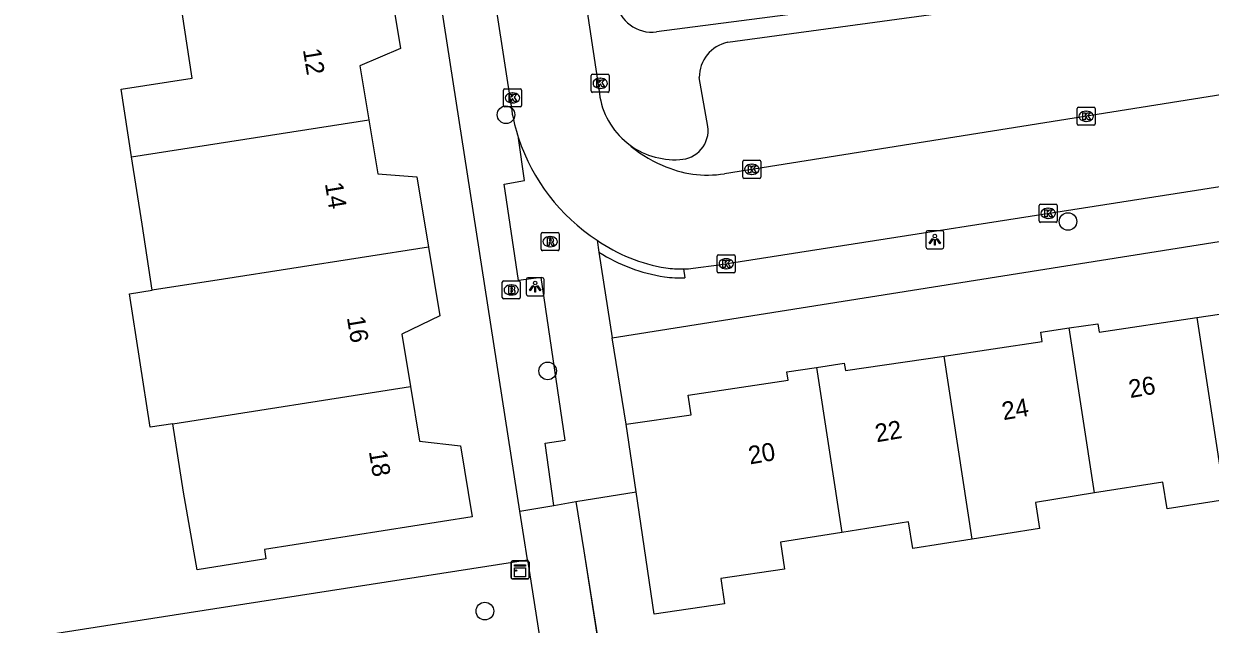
# Model space of a CAD drawing. Extents: x 160077 to 160945, y 386481 to 387498.
# Drawn here: x 160424.3 to 160490.2, y 387113 to 387146.3 of the extents above; entities that cross this region are included whole.
import ezdxf

# ---------------------------------------------------------------- set-up
doc = ezdxf.new("R2010")
doc.units = 0
for name, color, linetype in [('IMGEO_Boom', 7, 'Continuous'), ('IMGEO_Brandkraan', 7, 'Continuous'), ('IMGEO_Groenvoorziening', 7, 'Continuous'), ('IMGEO_Kast', 7, 'Continuous'), ('IMGEO_Kolk', 7, 'Continuous'), ('IMGEO_Lichtpunt', 7, 'Continuous'), ('IMGEO_Muur', 7, 'Continuous'), ('IMGEO_Pand', 7, 'Continuous'), ('IMGEO_Pand_nummerreeks', 7, 'Continuous'), ('IMGEO_Rijbaan_lokaal_open', 7, 'Continuous'), ('IMGEO_Rioolput', 7, 'Continuous'), ('IMGEO_Voetpad_open', 7, 'Continuous')]:
    doc.layers.add(name, color=color, linetype=linetype)

msp = doc.modelspace()

# ---------------------------------------------------------------- linework, layer by layer
at = {"layer": 'IMGEO_Boom'}
for centre in [(160451.086, 387141.291), (160482.283, 387135.372), (160453.398, 387127.085), (160449.914, 387113.767)]:
    msp.add_circle(centre, 0.489, dxfattribs=at)
at = {"layer": 'IMGEO_Brandkraan'}
for p, q in [((160450.879, 387131.15), (160450.879, 387132.002)), ((160450.954, 387132.076), (160451.806, 387132.076)), ((160451.88, 387132.002), (160451.88, 387131.15)), ((160451.39, 387131.296), (160451.365, 387131.296)), ((160451.367, 387131.856), (160451.392, 387131.856)), ((160451.806, 387131.076), (160450.954, 387131.076))]:
    msp.add_line(p, q, dxfattribs=at)
for points in [[(160450.879, 387131.15), (160450.879, 387132.002)], [(160450.954, 387132.076), (160451.806, 387132.076)], [(160451.88, 387132.002), (160451.88, 387131.15)], [(160451.227, 387131.776), (160451.227, 387131.376), (160451.44, 387131.376)], [(160451.458, 387131.776), (160451.227, 387131.776)], [(160451.406, 387131.695), (160451.352, 387131.695), (160451.352, 387131.619)], [(160451.352, 387131.619), (160451.405, 387131.619)], [(160451.414, 387131.543), (160451.352, 387131.543), (160451.352, 387131.462)], [(160451.352, 387131.462), (160451.414, 387131.462)], [(160451.806, 387131.076), (160450.954, 387131.076)]]:
    msp.add_lwpolyline(points, dxfattribs=at)
for centre, radius, start, end in [((160450.956, 387132), 0.0765, 91.55205, 178.44795), ((160450.956, 387132), 0.0765, 91.55205, 178.44795), ((160451.804, 387132), 0.0765, 1.55205, 88.44795), ((160451.804, 387132), 0.0765, 1.55205, 88.44795), ((160451.407, 387131.657), 0.0379, 267.82845, 90.93552), ((160451.415, 387131.502), 0.0404, 269.87594, 90.50774), ((160451.446, 387131.627), 0.251, 268.66757, 293.53466), ((160451.462, 387131.631), 0.145, 59.4692, 91.53667), ((160451.487, 387131.678), 0.0922, 285.51372, 58.15012), ((160451.492, 387131.486), 0.105, 301.31148, 78.98903), ((160450.956, 387131.152), 0.0765, 181.55205, 268.44795), ((160450.956, 387131.152), 0.0765, 181.55205, 268.44795), ((160451.804, 387131.152), 0.0765, 271.55205, 358.44795), ((160451.804, 387131.152), 0.0765, 271.55205, 358.44795)]:
    msp.add_arc(centre, radius, start, end, dxfattribs=at)
for centre, major_axis, ratio, start_param, end_param in [((160451.366, 387131.576), (-0.387, 0.002), 0.722429, 4.712389, 7.853982), ((160451.391, 387131.576), (-0.39, 0.002), 0.717154, 1.570796, 4.712389)]:
    msp.add_ellipse(centre, major_axis=major_axis, ratio=ratio, start_param=start_param, end_param=end_param, dxfattribs=at)
at = {"layer": 'IMGEO_Groenvoorziening'}
msp.add_lwpolyline([(160412.74, 387110.46), (160432.671, 387113.564), (160452.281, 387116.619)], dxfattribs=at)
at = {"layer": 'IMGEO_Kast'}
for p, q in [((160451.367, 387115.623), (160451.367, 387116.464)), ((160451.367, 387116.464), (160451.367, 387115.623)), ((160451.442, 387116.548), (160452.283, 387116.548)), ((160452.283, 387116.548), (160451.442, 387116.548)), ((160452.367, 387116.473), (160452.367, 387115.632)), ((160452.367, 387115.632), (160452.367, 387116.473)), ((160452.292, 387115.548), (160451.451, 387115.548)), ((160451.451, 387115.548), (160452.292, 387115.548))]:
    msp.add_line(p, q, dxfattribs=at)
for points in [[(160451.562, 387116.338), (160452.162, 387116.338), (160452.162, 387116.253), (160451.562, 387116.253), (160451.562, 387116.338)], [(160451.562, 387116.163), (160452.162, 387116.163), (160452.162, 387115.674), (160451.562, 387115.674), (160451.562, 387116.163)]]:
    msp.add_lwpolyline(points, dxfattribs=at)
msp.add_circle((160451.646, 387116.012), 0.0377, dxfattribs=at)
for centre, start, end in [((160451.445, 387116.47), 92.4484, 184.28452), ((160451.445, 387116.47), 92.4484, 184.28452), ((160452.289, 387116.47), 2.4484, 94.28452), ((160452.289, 387116.47), 2.4484, 94.28452), ((160451.445, 387115.626), 182.4484, 274.28452), ((160451.445, 387115.626), 182.4484, 274.28452), ((160452.289, 387115.626), 272.4484, 4.28452), ((160452.289, 387115.626), 272.4484, 4.28452)]:
    msp.add_arc(centre, 0.0779, start, end, dxfattribs=at)
at = {"layer": 'IMGEO_Kolk'}
for p, q in [((160455.816, 387142.609), (160455.816, 387143.461)), ((160455.891, 387143.535), (160456.743, 387143.535)), ((160456.304, 387143.315), (160456.329, 387143.315)), ((160456.817, 387143.461), (160456.817, 387142.609)), ((160450.946, 387141.799), (160450.946, 387142.651)), ((160451.021, 387142.725), (160451.873, 387142.725)), ((160451.434, 387142.505), (160451.459, 387142.505)), ((160451.947, 387142.651), (160451.947, 387141.799)), ((160456.743, 387142.535), (160455.891, 387142.535)), ((160456.327, 387142.755), (160456.302, 387142.755)), ((160451.457, 387141.945), (160451.432, 387141.945)), ((160451.873, 387141.725), (160451.021, 387141.725)), ((160482.789, 387140.78), (160482.789, 387141.632)), ((160482.864, 387141.706), (160483.716, 387141.706)), ((160483.277, 387141.486), (160483.302, 387141.486)), ((160483.79, 387141.632), (160483.79, 387140.78)), ((160483.716, 387140.706), (160482.864, 387140.706)), ((160483.3, 387140.926), (160483.275, 387140.926)), ((160464.231, 387137.838), (160464.231, 387138.69)), ((160464.306, 387138.764), (160465.158, 387138.764)), ((160464.719, 387138.544), (160464.744, 387138.544)), ((160465.232, 387138.69), (160465.232, 387137.838)), ((160464.742, 387137.984), (160464.717, 387137.984)), ((160465.158, 387137.764), (160464.306, 387137.764)), ((160480.685, 387135.4), (160480.685, 387136.252)), ((160480.76, 387136.326), (160481.612, 387136.326)), ((160481.173, 387136.106), (160481.198, 387136.106)), ((160481.686, 387136.252), (160481.686, 387135.4)), ((160481.612, 387135.326), (160480.76, 387135.326)), ((160481.196, 387135.546), (160481.171, 387135.546)), ((160462.811, 387132.602), (160462.811, 387133.454)), ((160462.886, 387133.528), (160463.738, 387133.528)), ((160463.299, 387133.308), (160463.324, 387133.308)), ((160463.812, 387133.454), (160463.812, 387132.602)), ((160463.322, 387132.748), (160463.297, 387132.748)), ((160463.738, 387132.528), (160462.886, 387132.528))]:
    msp.add_line(p, q, dxfattribs=at)
for points in [[(160455.816, 387142.609), (160455.816, 387143.461)], [(160455.891, 387143.535), (160456.743, 387143.535)], [(160456.137, 387143.235), (160456.26, 387143.235), (160456.26, 387143.084), (160456.39, 387143.235), (160456.554, 387143.235), (160456.408, 387143.084), (160456.561, 387142.835), (160456.409, 387142.835), (160456.324, 387142.999), (160456.26, 387142.932), (160456.26, 387142.835), (160456.137, 387142.835), (160456.137, 387143.235)], [(160456.817, 387143.461), (160456.817, 387142.609)], [(160450.946, 387141.799), (160450.946, 387142.651)], [(160451.021, 387142.725), (160451.873, 387142.725)], [(160451.947, 387142.651), (160451.947, 387141.799)], [(160456.743, 387142.535), (160455.891, 387142.535)], [(160451.267, 387142.425), (160451.39, 387142.425), (160451.39, 387142.274), (160451.52, 387142.425), (160451.684, 387142.425), (160451.538, 387142.274), (160451.691, 387142.025), (160451.539, 387142.025), (160451.454, 387142.189), (160451.39, 387142.122), (160451.39, 387142.025), (160451.267, 387142.025), (160451.267, 387142.425)], [(160451.873, 387141.725), (160451.021, 387141.725)], [(160482.789, 387140.78), (160482.789, 387141.632)], [(160482.864, 387141.706), (160483.716, 387141.706)], [(160483.11, 387141.406), (160483.233, 387141.406), (160483.233, 387141.255), (160483.363, 387141.406), (160483.527, 387141.406), (160483.381, 387141.255), (160483.534, 387141.006), (160483.382, 387141.006), (160483.297, 387141.17), (160483.233, 387141.103), (160483.233, 387141.006), (160483.11, 387141.006), (160483.11, 387141.406)], [(160483.79, 387141.632), (160483.79, 387140.78)], [(160483.716, 387140.706), (160482.864, 387140.706)], [(160464.231, 387137.838), (160464.231, 387138.69)], [(160464.306, 387138.764), (160465.158, 387138.764)], [(160465.232, 387138.69), (160465.232, 387137.838)], [(160464.552, 387138.464), (160464.675, 387138.464), (160464.675, 387138.313), (160464.805, 387138.464), (160464.969, 387138.464), (160464.823, 387138.313), (160464.976, 387138.064), (160464.824, 387138.064), (160464.739, 387138.228), (160464.675, 387138.161), (160464.675, 387138.064), (160464.552, 387138.064), (160464.552, 387138.464)], [(160465.158, 387137.764), (160464.306, 387137.764)], [(160480.685, 387135.4), (160480.685, 387136.252)], [(160480.76, 387136.326), (160481.612, 387136.326)], [(160481.006, 387136.026), (160481.129, 387136.026), (160481.129, 387135.875), (160481.259, 387136.026), (160481.423, 387136.026), (160481.277, 387135.875), (160481.43, 387135.626), (160481.278, 387135.626), (160481.193, 387135.79), (160481.129, 387135.723), (160481.129, 387135.626), (160481.006, 387135.626), (160481.006, 387136.026)], [(160481.686, 387136.252), (160481.686, 387135.4)], [(160481.612, 387135.326), (160480.76, 387135.326)], [(160462.811, 387132.602), (160462.811, 387133.454)], [(160462.886, 387133.528), (160463.738, 387133.528)], [(160463.812, 387133.454), (160463.812, 387132.602)], [(160463.132, 387133.228), (160463.255, 387133.228), (160463.255, 387133.077), (160463.385, 387133.228), (160463.549, 387133.228), (160463.403, 387133.077), (160463.556, 387132.828), (160463.404, 387132.828), (160463.319, 387132.992), (160463.255, 387132.925), (160463.255, 387132.828), (160463.132, 387132.828), (160463.132, 387133.228)], [(160463.738, 387132.528), (160462.886, 387132.528)]]:
    msp.add_lwpolyline(points, dxfattribs=at)
for centre, start, end in [((160455.893, 387143.459), 91.55205, 178.44795), ((160455.893, 387143.459), 91.55205, 178.44795), ((160456.741, 387143.459), 1.55205, 88.44795), ((160456.741, 387143.459), 1.55205, 88.44795), ((160451.023, 387142.649), 91.55205, 178.44795), ((160451.023, 387142.649), 91.55205, 178.44795), ((160451.871, 387142.649), 1.55205, 88.44795), ((160451.871, 387142.649), 1.55205, 88.44795), ((160455.893, 387142.611), 181.55205, 268.44795), ((160455.893, 387142.611), 181.55205, 268.44795), ((160456.741, 387142.611), 271.55205, 358.44795), ((160456.741, 387142.611), 271.55205, 358.44795), ((160451.023, 387141.801), 181.55205, 268.44795), ((160451.023, 387141.801), 181.55205, 268.44795), ((160451.871, 387141.801), 271.55205, 358.44795), ((160451.871, 387141.801), 271.55205, 358.44795), ((160482.866, 387141.63), 91.55205, 178.44795), ((160482.866, 387141.63), 91.55205, 178.44795), ((160483.714, 387141.63), 1.55205, 88.44795), ((160483.714, 387141.63), 1.55205, 88.44795), ((160482.866, 387140.782), 181.55205, 268.44795), ((160482.866, 387140.782), 181.55205, 268.44795), ((160483.714, 387140.782), 271.55205, 358.44795), ((160483.714, 387140.782), 271.55205, 358.44795), ((160464.308, 387138.688), 91.55205, 178.44795), ((160464.308, 387138.688), 91.55205, 178.44795), ((160465.156, 387138.688), 1.55205, 88.44795), ((160465.156, 387138.688), 1.55205, 88.44795), ((160464.308, 387137.84), 181.55205, 268.44795), ((160464.308, 387137.84), 181.55205, 268.44795), ((160465.156, 387137.84), 271.55205, 358.44795), ((160465.156, 387137.84), 271.55205, 358.44795), ((160480.762, 387136.25), 91.55205, 178.44795), ((160480.762, 387136.25), 91.55205, 178.44795), ((160481.61, 387136.25), 1.55205, 88.44795), ((160481.61, 387136.25), 1.55205, 88.44795), ((160480.762, 387135.402), 181.55205, 268.44795), ((160480.762, 387135.402), 181.55205, 268.44795), ((160481.61, 387135.402), 271.55205, 358.44795), ((160481.61, 387135.402), 271.55205, 358.44795), ((160462.888, 387133.452), 91.55205, 178.44795), ((160462.888, 387133.452), 91.55205, 178.44795), ((160463.736, 387133.452), 1.55205, 88.44795), ((160463.736, 387133.452), 1.55205, 88.44795), ((160462.888, 387132.604), 181.55205, 268.44795), ((160462.888, 387132.604), 181.55205, 268.44795), ((160463.736, 387132.604), 271.55205, 358.44795), ((160463.736, 387132.604), 271.55205, 358.44795)]:
    msp.add_arc(centre, 0.0765, start, end, dxfattribs=at)
for centre, major_axis, ratio, start_param, end_param in [((160456.303, 387143.035), (-0.387, 0.002), 0.722429, 4.712389, 7.853982), ((160456.328, 387143.035), (-0.39, 0.002), 0.717154, 1.570796, 4.712389), ((160451.433, 387142.225), (-0.387, 0.002), 0.722429, 4.712389, 7.853982), ((160451.458, 387142.225), (-0.39, 0.002), 0.717154, 1.570796, 4.712389), ((160483.276, 387141.206), (-0.387, 0.002), 0.722429, 4.712389, 7.853982), ((160483.301, 387141.206), (-0.39, 0.002), 0.717154, 1.570796, 4.712389), ((160464.718, 387138.264), (-0.387, 0.002), 0.722429, 4.712389, 7.853982), ((160464.743, 387138.264), (-0.39, 0.002), 0.717154, 1.570796, 4.712389), ((160481.172, 387135.826), (-0.387, 0.002), 0.722429, 4.712389, 7.853982), ((160481.197, 387135.826), (-0.39, 0.002), 0.717154, 1.570796, 4.712389), ((160463.298, 387133.028), (-0.387, 0.002), 0.722429, 4.712389, 7.853982), ((160463.323, 387133.028), (-0.39, 0.002), 0.717154, 1.570796, 4.712389)]:
    msp.add_ellipse(centre, major_axis=major_axis, ratio=ratio, start_param=start_param, end_param=end_param, dxfattribs=at)
at = {"layer": 'IMGEO_Lichtpunt'}
for p, q in [((160474.395, 387134.766), (160474.395, 387133.959)), ((160474.395, 387134.766), (160474.395, 387133.959)), ((160475.297, 387134.861), (160474.489, 387134.861)), ((160475.297, 387134.861), (160474.489, 387134.861)), ((160475.391, 387133.959), (160475.391, 387134.766)), ((160475.391, 387133.959), (160475.391, 387134.766)), ((160474.489, 387133.865), (160475.297, 387133.865)), ((160474.489, 387133.865), (160475.297, 387133.865)), ((160452.207, 387132.16), (160452.207, 387131.353)), ((160452.207, 387132.16), (160452.207, 387131.353)), ((160453.109, 387132.255), (160452.301, 387132.255)), ((160453.109, 387132.255), (160452.301, 387132.255)), ((160453.203, 387131.353), (160453.203, 387132.16)), ((160453.203, 387131.353), (160453.203, 387132.16)), ((160452.301, 387131.259), (160453.109, 387131.259)), ((160452.301, 387131.259), (160453.109, 387131.259))]:
    msp.add_line(p, q, dxfattribs=at)
for points in [[(160474.769, 387134.43), (160474.808, 387134.402), (160474.62, 387134.14), (160474.582, 387134.167), (160474.769, 387134.43)], [(160474.871, 387134.382), (160474.918, 387134.382), (160474.918, 387134.06), (160474.871, 387134.06), (160474.871, 387134.382)], [(160474.981, 387134.402), (160475.019, 387134.429), (160475.206, 387134.167), (160475.167, 387134.139), (160474.981, 387134.402)], [(160452.581, 387131.824), (160452.62, 387131.796), (160452.432, 387131.534), (160452.394, 387131.561), (160452.581, 387131.824)], [(160452.683, 387131.776), (160452.73, 387131.776), (160452.73, 387131.454), (160452.683, 387131.454), (160452.683, 387131.776)], [(160452.793, 387131.796), (160452.831, 387131.823), (160453.018, 387131.561), (160452.979, 387131.533), (160452.793, 387131.796)]]:
    msp.add_lwpolyline(points, dxfattribs=at)
for centre in [(160474.894, 387134.564), (160452.706, 387131.958)]:
    msp.add_circle(centre, 0.0994, dxfattribs=at)
for centre, start, end in [((160474.489, 387134.766), 90, 180), ((160474.489, 387134.766), 90, 180), ((160475.297, 387134.766), 0, 90), ((160475.297, 387134.766), 0, 90), ((160474.489, 387133.959), 180, 270), ((160474.489, 387133.959), 180, 270), ((160475.297, 387133.959), 270, 0), ((160475.297, 387133.959), 270, 360), ((160452.301, 387132.16), 90, 180), ((160452.301, 387132.16), 90, 180), ((160453.109, 387132.16), 0, 90), ((160453.109, 387132.16), 0, 90), ((160452.301, 387131.353), 180, 270), ((160452.301, 387131.353), 180, 270), ((160453.109, 387131.353), 270, 0), ((160453.109, 387131.353), 270, 360)]:
    msp.add_arc(centre, 0.0946, start, end, dxfattribs=at)
at = {"layer": 'IMGEO_Muur'}
for points in [[(160454.971, 387119.846), (160455.401, 387117.108)], [(160455.401, 387117.108), (160457.188, 387105.719)]]:
    msp.add_lwpolyline(points, dxfattribs=at)
at = {"layer": 'IMGEO_Pand'}
for points in [[(160444.601, 387148.767), (160445.225, 387144.974), (160442.979, 387144.007), (160443.472, 387141.013)], [(160430.301, 387138.954), (160429.721, 387142.701), (160433.668, 387143.313), (160433.102, 387146.97)], [(160430.301, 387138.954), (160443.472, 387141.013)], [(160443.472, 387141.013), (160443.966, 387138.009), (160446.142, 387137.858), (160446.784, 387133.953)], [(160431.445, 387131.563), (160430.88, 387135.215), (160430.301, 387138.954)], [(160446.784, 387133.953), (160435.399, 387132.176), (160431.445, 387131.563)], [(160446.784, 387133.953), (160447.413, 387130.132), (160445.304, 387129.125), (160445.782, 387126.219)], [(160432.592, 387124.157), (160431.33, 387123.96), (160430.182, 387131.367), (160431.445, 387131.563)], [(160489.438, 387130.043), (160494.84, 387130.838), (160494.751, 387131.443), (160496.365, 387131.68)], [(160482.346, 387129.471), (160483.941, 387129.706), (160484.009, 387129.244), (160489.438, 387130.043)], [(160489.438, 387130.043), (160490.998, 387119.945)], [(160475.405, 387127.91), (160480.851, 387128.712), (160480.774, 387129.24), (160482.346, 387129.471)], [(160483.758, 387120.32), (160482.346, 387129.471)], [(160468.321, 387127.284), (160469.866, 387127.512), (160469.926, 387127.104), (160475.405, 387127.91)], [(160476.973, 387117.758), (160475.405, 387127.91)], [(160457.765, 387124.128), (160461.361, 387124.657), (160461.2, 387125.75), (160466.747, 387126.567), (160466.677, 387127.042), (160468.321, 387127.284)], [(160468.321, 387127.284), (160469.734, 387118.133)], [(160445.782, 387126.219), (160446.279, 387123.196), (160448.561, 387122.938), (160449.208, 387119.002), (160437.679, 387117.185), (160437.762, 387116.659), (160433.946, 387116.058), (160433.178, 387120.359), (160432.592, 387124.157)], [(160432.592, 387124.157), (160445.782, 387126.219)], [(160458.316, 387120.383), (160457.765, 387124.128)], [(160490.998, 387119.945), (160487.795, 387119.434), (160487.557, 387120.926), (160483.758, 387120.32)], [(160469.734, 387118.133), (160466.327, 387117.589), (160466.547, 387116.089), (160463.009, 387115.568), (160463.214, 387114.174), (160459.314, 387113.6), (160458.316, 387120.383)], [(160483.758, 387120.32), (160480.475, 387119.796), (160480.707, 387118.354), (160476.973, 387117.758)], [(160476.973, 387117.758), (160473.676, 387117.232), (160473.438, 387118.724), (160469.734, 387118.133)]]:
    msp.add_lwpolyline(points, dxfattribs=at)
at = {"layer": 'IMGEO_Rijbaan_lokaal_open'}
for points in [[(160451.698, 387172.524), (160452.642, 387166.52), (160456.269, 387142.466)], [(160450.551, 387147.034), (160451.402, 387141.525)], [(160493.782, 387142.868), (160463.21, 387138.021)], [(160461.484, 387132.784), (160462.906, 387132.966), (160489.417, 387137.116), (160500, 387138.779), (160517.735, 387141.567), (160517.975, 387141.6)]]:
    msp.add_lwpolyline(points, dxfattribs=at)
for centre, radius, start, end in [((160460.454, 387143.021), 4.222, 187.55604, 231.31026), ((160461.862, 387143.319), 10.613, 189.73472, 198.24958), ((160461.962, 387143.341), 10.714, 198.19124, 237.09964), ((160462.553, 387145.045), 7.124, 228.30917, 246.94278), ((160462.263, 387143.954), 6.008, 245.40567, 279.06548), ((160461.321, 387141.648), 8.953, 234.65434, 261.2468), ((160460.777, 387138.613), 5.871, 261.99122, 271.59089), ((160460.826, 387138.018), 5.276, 271.24201, 277.16871)]:
    msp.add_arc(centre, radius, start, end, dxfattribs=at)
at = {"layer": 'IMGEO_Rioolput'}
for p, q in [((160453.036, 387133.829), (160453.036, 387134.681)), ((160453.111, 387134.755), (160453.963, 387134.755)), ((160454.037, 387134.681), (160454.037, 387133.829)), ((160453.547, 387133.975), (160453.522, 387133.975)), ((160453.524, 387134.535), (160453.549, 387134.535)), ((160453.963, 387133.755), (160453.111, 387133.755))]:
    msp.add_line(p, q, dxfattribs=at)
for points in [[(160453.036, 387133.829), (160453.036, 387134.681)], [(160453.111, 387134.755), (160453.963, 387134.755)], [(160454.037, 387134.681), (160454.037, 387133.829)], [(160453.625, 387134.453), (160453.373, 387134.455), (160453.373, 387134.055)], [(160453.373, 387134.055), (160453.497, 387134.055), (160453.497, 387134.217), (160453.508, 387134.217)], [(160453.551, 387134.374), (160453.497, 387134.374), (160453.497, 387134.293)], [(160453.497, 387134.293), (160453.549, 387134.293)], [(160453.555, 387134.188), (160453.626, 387134.055), (160453.766, 387134.055), (160453.701, 387134.181)], [(160453.963, 387133.755), (160453.111, 387133.755)]]:
    msp.add_lwpolyline(points, dxfattribs=at)
for centre, radius, start, end in [((160453.113, 387134.679), 0.0765, 91.55205, 178.44795), ((160453.113, 387134.679), 0.0765, 91.55205, 178.44795), ((160453.961, 387134.679), 0.0765, 1.55205, 88.44795), ((160453.961, 387134.679), 0.0765, 1.55205, 88.44795), ((160453.507, 387134.164), 0.0533, 26.02933, 88.69889), ((160453.533, 387134.482), 0.19, 274.7715, 282.96867), ((160453.557, 387134.278), 0.0964, 77.00612, 93.18647), ((160453.571, 387134.335), 0.0378, 276.66336, 79.67722), ((160453.624, 387134.343), 0.109, 350.36119, 89.41601), ((160453.622, 387134.343), 0.112, 277.58423, 350.98172), ((160453.606, 387134.128), 0.108, 29.51342, 73.79051), ((160453.113, 387133.831), 0.0765, 181.55205, 268.44795), ((160453.113, 387133.831), 0.0765, 181.55205, 268.44795), ((160453.961, 387133.831), 0.0765, 271.55205, 358.44795), ((160453.961, 387133.831), 0.0765, 271.55205, 358.44795)]:
    msp.add_arc(centre, radius, start, end, dxfattribs=at)
for centre, major_axis, ratio, start_param, end_param in [((160453.523, 387134.255), (-0.387, 0.002), 0.722429, 4.712389, 7.853982), ((160453.548, 387134.255), (-0.39, 0.002), 0.717154, 1.570796, 4.712389)]:
    msp.add_ellipse(centre, major_axis=major_axis, ratio=ratio, start_param=start_param, end_param=end_param, dxfattribs=at)
at = {"layer": 'IMGEO_Voetpad_open'}
for points in [[(160451.862, 387119.314), (160440.112, 387194.954), (160439.602, 387197.252)], [(160487.035, 387149.659), (160476.173, 387148.072), (160459.449, 387145.885)], [(160463.394, 387145.308), (160489.513, 387148.892)], [(160462.291, 387140.644), (160461.812, 387143.354)], [(160453.744, 387119.63), (160453.264, 387123.077), (160454.373, 387123.247), (160453.032, 387132.259), (160451.773, 387132.109), (160450.991, 387137.444), (160452.121, 387137.644), (160451.783, 387139.996)], [(160456.983, 387128.917), (160500, 387135.737), (160518.16, 387138.589)], [(160456.142, 387134.345), (160456.246, 387133.673)], [(160456.246, 387133.673), (160456.983, 387128.917)], [(160460.94, 387132.744), (160461.02, 387132.246)], [(160457.765, 387124.128), (160456.983, 387128.917)], [(160454.971, 387119.846), (160458.316, 387120.383)], [(160451.862, 387119.314), (160453.744, 387119.63)], [(160453.744, 387119.63), (160454.971, 387119.846)], [(160454.971, 387119.846), (160455.401, 387117.108), (160456.412, 387110.822)], [(160452.281, 387116.619), (160452.082, 387117.899), (160451.862, 387119.314)], [(160452.281, 387116.619), (160453.551, 387108.448)]]:
    msp.add_lwpolyline(points, dxfattribs=at)
for centre, radius, start, end in [((160459.187, 387147.885), 2.017, 188.91775, 277.45642), ((160463.806, 387143.357), 1.994, 101.93218, 180.07908), ((160460.693, 387140.42), 1.614, 271.35496, 7.9685), ((160460.459, 387143.03), 4.232, 231.33188, 273.68282), ((160461.333, 387141.673), 9.48, 237.54617, 261.20024), ((160460.779, 387138.7), 6.459, 262.02348, 272.13611)]:
    msp.add_arc(centre, radius, start, end, dxfattribs=at)

# ---------------------------------------------------------------- texts
at = {"layer": 'IMGEO_Pand_nummerreeks'}
for s, rotation, p in [('12', 279.33701, (160439.807, 387144.903)), ('14', 279.33701, (160441.029, 387137.477)), ('16', 279.339, (160442.248, 387130.052)), ('26', 9.88745, (160485.738, 387125.577)), ('24', 9.88745, (160478.702, 387124.35)), ('22', 9.88745, (160471.662, 387123.123)), ('20', 9.88745, (160464.631, 387121.897)), ('18', 279.33701, (160443.47, 387122.625))]:
    msp.add_text(s, height=1, rotation=rotation, dxfattribs=at).set_placement(p)

doc.saveas('drawing.dxf')
